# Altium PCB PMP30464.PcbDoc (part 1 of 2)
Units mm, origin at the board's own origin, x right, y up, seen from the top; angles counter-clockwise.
Board outline 89.03 x 50.29 mm, 4 copper layers (Top Layer, GND, Signal Layer, Bottom Layer), stack 2.028 mm thick; 80 components, 45 nets, 213 pads, 174 vias.
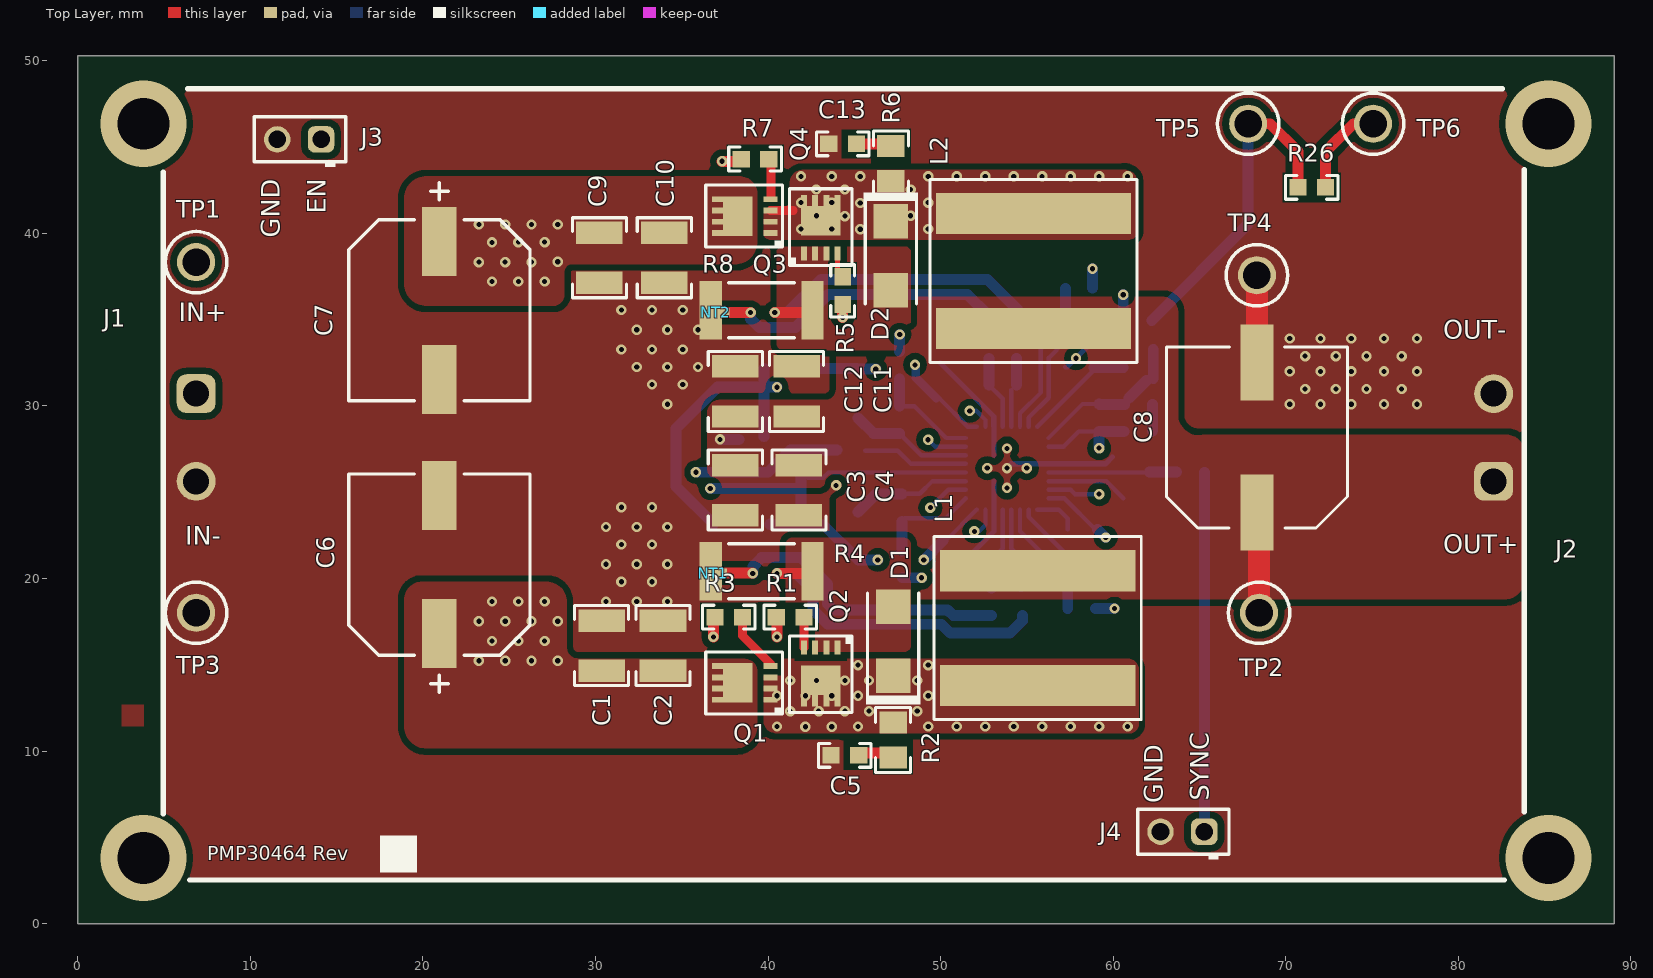
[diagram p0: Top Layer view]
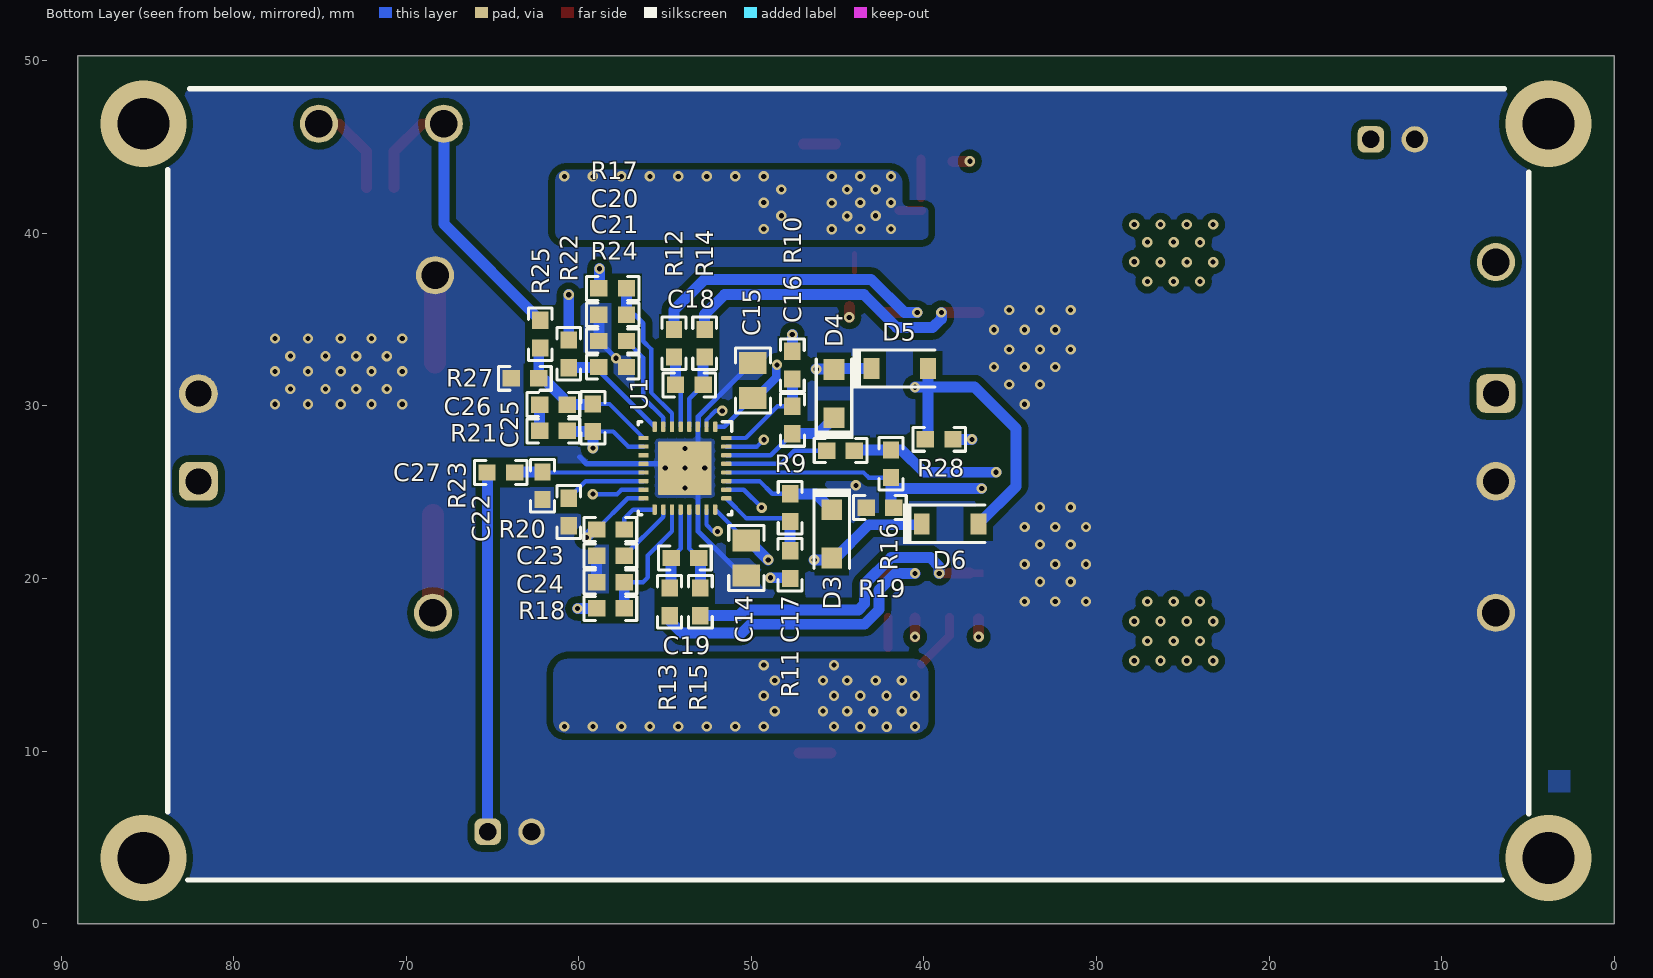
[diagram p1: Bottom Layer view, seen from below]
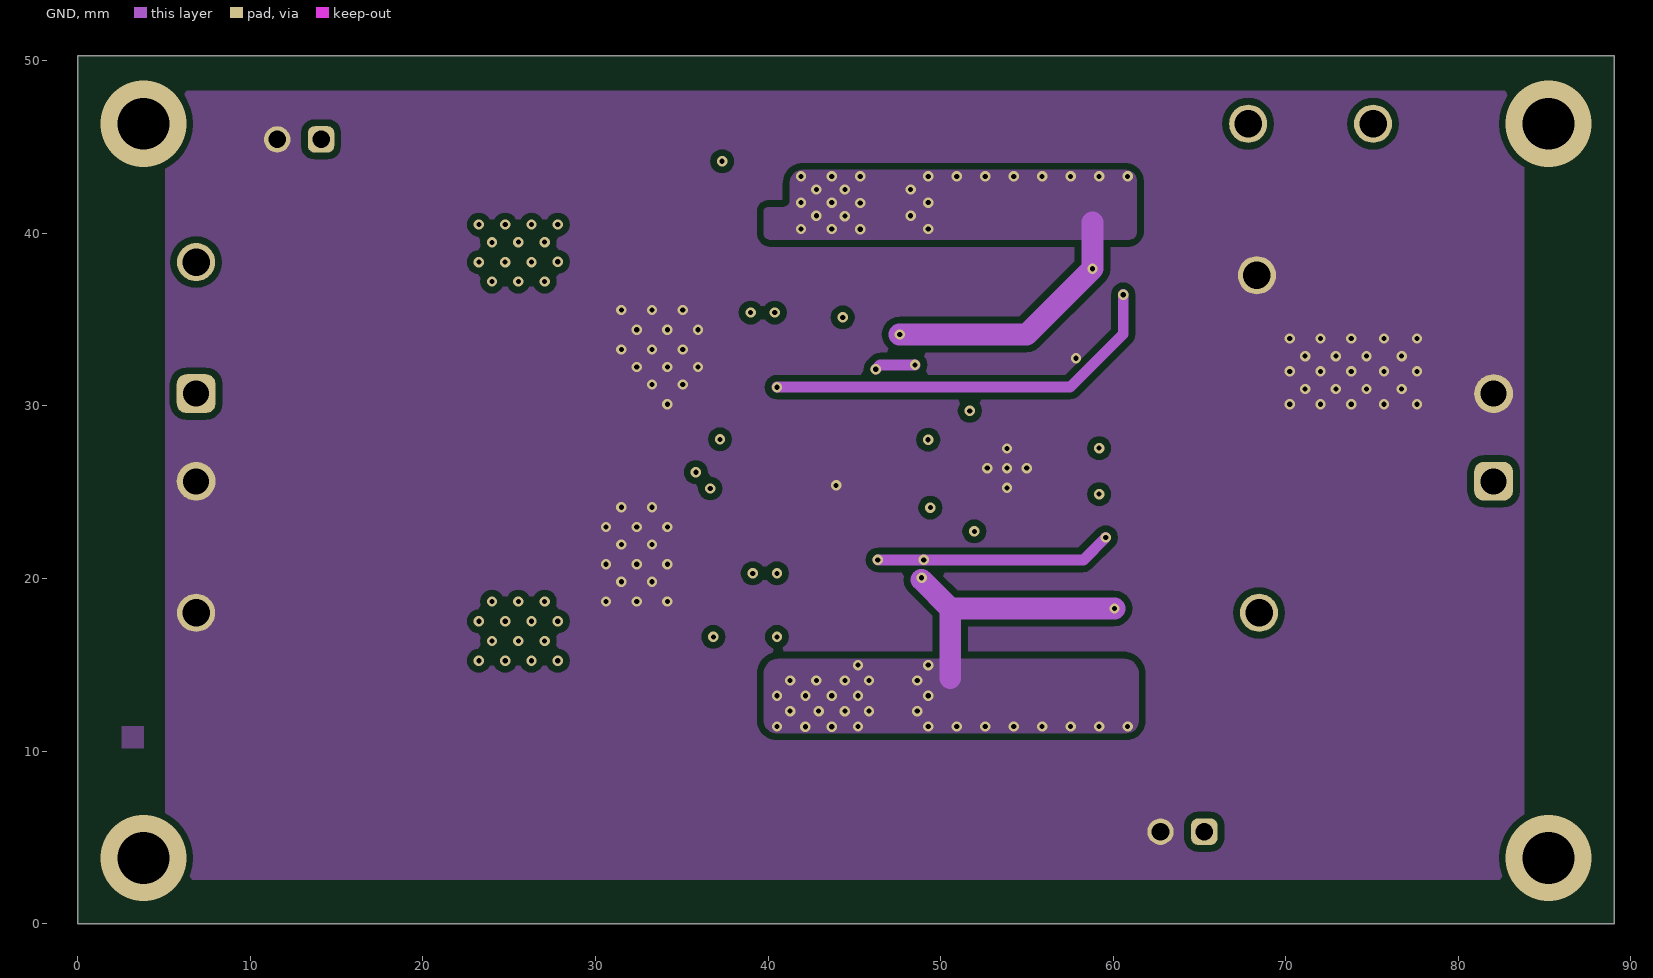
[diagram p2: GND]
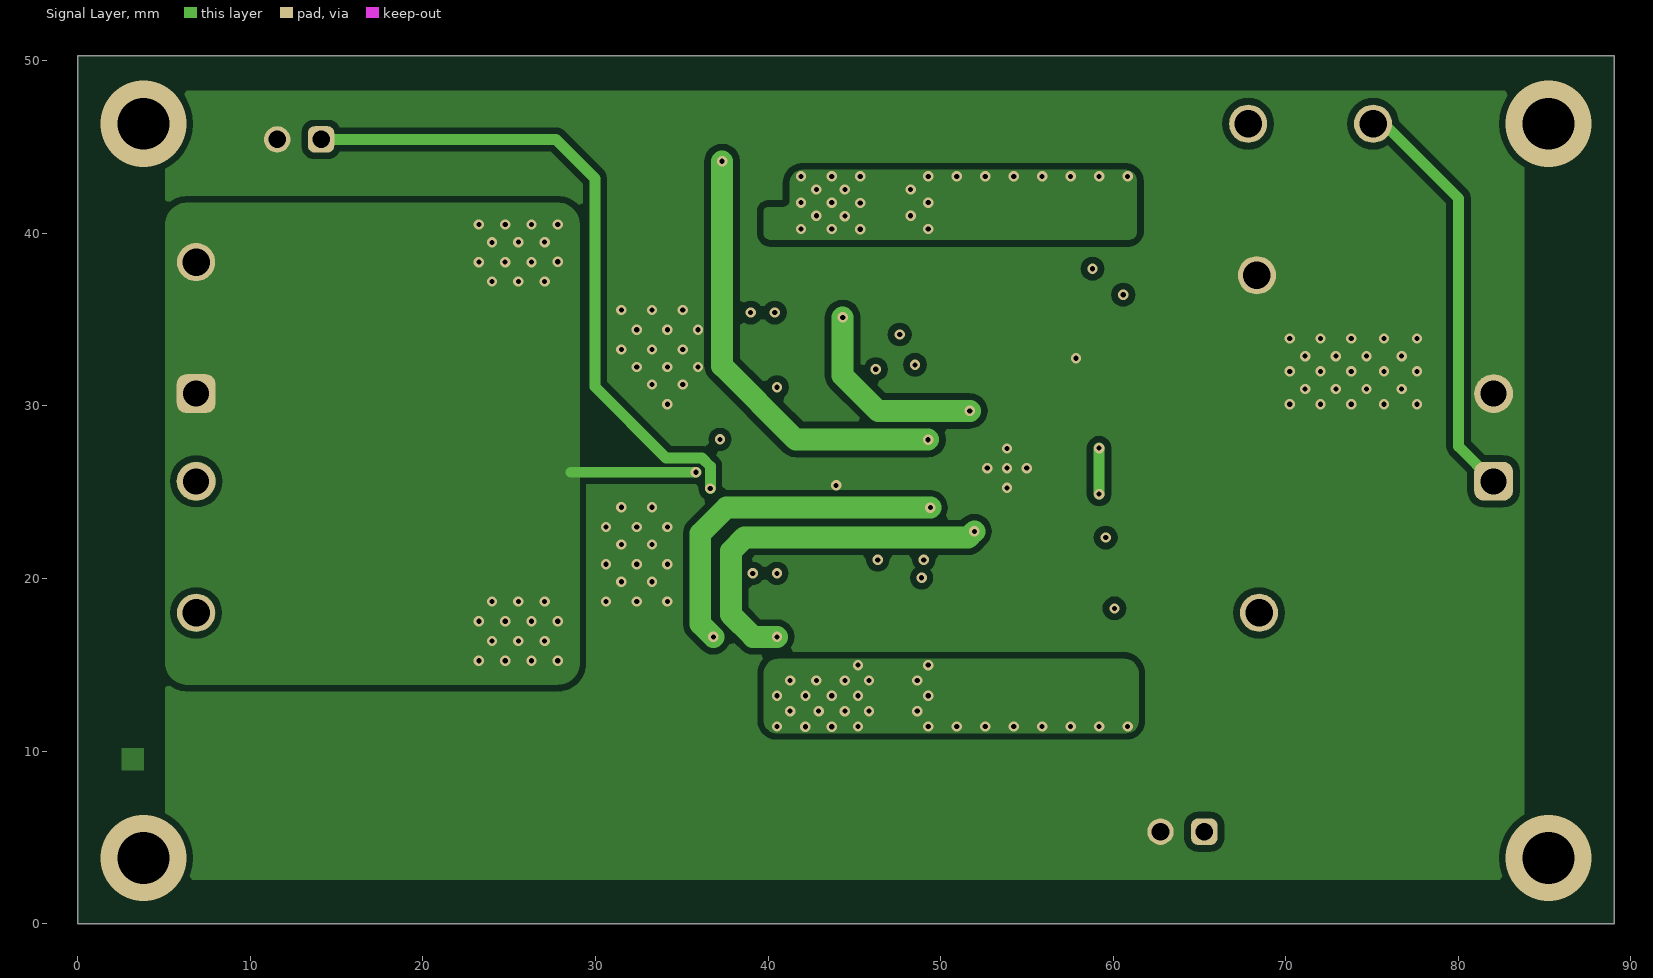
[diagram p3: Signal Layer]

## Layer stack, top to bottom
Top Solder: solder mask 0.0102, Solder Resist, Dk 3.5
Top Layer: signal copper 0.0356
Dielectric1: core 1.5037, FR-4, Dk 4.8
GND: signal copper 0.036
Dielectric 3: prepreg 0.127, Dk 4.2
Signal Layer: signal copper 0.036
Dielectric 2: core 0.254, Dk 4.2
Bottom Layer: signal copper 0.0356
Bottom Solder: solder mask 0.0102, Solder Resist, Dk 3.5

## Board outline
0,0 89.027,0 89.027,50.292 0,50.292

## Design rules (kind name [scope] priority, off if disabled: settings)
AcuteAngle [All] p1: minimum=4.50000000000000E+0001 checktracksonly=FALSE
AssemblyTestPointUsage [All] p1: valid=2
Clearance Clearance_Keepouts [((IsTrack Or IsArc) And Not InPoly) And IsFree and IsKeepOut vs ((IsTrack Or IsArc) And Not InPoly) And IsFree and IsKeepOut] p1: gap=0 ignorepadtopadclearanceinfootprint=FALSE
Clearance Clearance_BoardEdge_MountingHoles [OnCopper and InComponentClass('Mounting Holes') vs IsKeepOut] p2: gap=1.016 ignorepadtopadclearanceinfootprint=FALSE except(0: Arc-Hole Track-Hole SMDPad-Hole THPad-Hole Via-Hole Fill-Hole Poly-Hole Region-Hole Text-Hole)
Clearance Clearance_BoardEdge_Poly [OnCopper and InPoly vs IsKeepOut] p3: gap=0.635 ignorepadtopadclearanceinfootprint=FALSE except(0: Arc-Hole Track-Hole SMDPad-Hole THPad-Hole Via-Hole Fill-Hole Poly-Hole Region-Hole Text-Hole)
Clearance Clearance_BoardEdge [OnCopper and Not InComponentClass('Logo') and not InComponentClass('FiducialMark') and not InRegion(1000,500,4000,800) and Not IsKeepout vs IsKeepOut] p4: gap=1.905 ignorepadtopadclearanceinfootprint=FALSE except(0: Arc-Hole Track-Hole SMDPad-Hole THPad-Hole Via-Hole Fill-Hole Poly-Hole Region-Hole Text-Hole)
Clearance Clearance_Poly [InPolygon] p5: gap=0.381 ignorepadtopadclearanceinfootprint=FALSE except(0: Arc-Hole Track-Hole SMDPad-Hole THPad-Hole Via-Hole Fill-Hole Poly-Hole Region-Hole Text-Hole)
Clearance [All] p6: gap=0.2 ignorepadtopadclearanceinfootprint=FALSE except(0: Arc-Hole Track-Hole SMDPad-Hole THPad-Hole Via-Hole Fill-Hole Poly-Hole Region-Hole Text-Hole)
ComponentClearance ComponentClearance_MountingHoles_FiducialMarks [InComponentClass('Mounting Holes') vs InComponentClass('FiducialMark')] p1: gap=1.27 collisioncheckmode=3 verticalgap=0.254 showdistances=FALSE
ComponentClearance ComponentClearance_Shunt [InComponentClass('Header') vs InComponentClass('Shunt')] p2: gap=0 collisioncheckmode=3 verticalgap=0 showdistances=FALSE
ComponentClearance ComponentClearance_Logo [InComponentClass('Logo')] p3: gap=1.27 collisioncheckmode=3 verticalgap=0.254 showdistances=FALSE
ComponentClearance ComponentClearance_ScrewToNut [(HasFootprint('NY PMS 440 0025 PH')) vs (HasFootprint('Keystone_1902C'))] p4: gap=0.127 collisioncheckmode=3 verticalgap=0.254 showdistances=FALSE
ComponentClearance ComponentClearance_MountingHoles [InComponentClass('Mounting Holes')] p5: gap=6.35 collisioncheckmode=3 verticalgap=2540 showdistances=FALSE
ComponentClearance ComponentClearance_SmallPassives [HasFootprint('0201*') or HasFootprint('0402*') or HasFootprint('0508') or HasFootprint('0603*') or HasFootprint('0612') or HasFootprint('0805*') or HasFootprint('0815*') or HasFootprint('0830*') or HasFootprint('1206*') or HasFootprint('1210*') or HasFootprint('1808*') or HasFootprint('1812*') or HasFootprint('1825*') or HasFootprint('2010*') or HasFootprint('2220*') or HasFootprint('2225*') or HasFootprint('2512*') or HasFootprint('2728*') or HasFootprint('3518*') vs HasFootprint('0201*') or HasFootprint('0402*') or HasFootprint('0508') or HasFootprint('0603*') or HasFootprint('0612') or HasFootprint('0805*') or HasFootprint('0815*') or HasFootprint('0830*') or HasFootprint('1206*') or HasFootprint('1210*') or HasFootprint('1808*') or HasFootprint('1812*') or HasFootprint('1825*') or HasFootprint('2010*') or HasFootprint('2220*') or HasFootprint('2225*') or HasFootprint('2512*') or HasFootprint('2728*') or HasFootprint('3518*')] p6: gap=0.508 collisioncheckmode=3 verticalgap=0.254 showdistances=FALSE
ComponentClearance ComponentClearance_THtoSMT [IsThruComponent vs IsSMTComponent] p7: gap=2.54 collisioncheckmode=3 verticalgap=0.762 showdistances=FALSE
ComponentClearance ComponentClearance_THtoTH [IsThruComponent vs IsThruComponent] p8: gap=3 collisioncheckmode=3 verticalgap=0.762 showdistances=FALSE
ComponentClearance [All] p9: gap=1.016 collisioncheckmode=3 verticalgap=0.254 showdistances=FALSE
DiffPairsRouting [All] p1: maxlimit=2.54 minlimit=0.254 mostfreqgap=0.254 toplayer_minwidth=0.381 toplayer_maxwidth=0.381 toplayer_prefwidth=0.381 midlayer1_minwidth=0.381 midlayer1_maxwidth=0.381 midlayer1_prefwidth=0.381 midlayer2_minwidth=0.381 midlayer2_maxwidth=0.381 midlayer2_prefwidth=0.381 bottomlayer_minwidth=0.381 bottomlayer_maxwidth=0.381 bottomlayer_prefwidth=0.381 maxuncoupledlength=25.4
FabricationTestPointUsage TestPointUsage [All] p1: valid=2 allowmultiple=FALSE
FabricationTestpoint Testpoint [All] p1: side=3 testpointundercomponent=TRUE minsize=1.016 maxsize=2.54 preferedsize=1.524 minholesize=0 maxholesize=1.016 preferedholesize=0.813 testpointgrid=0.025 allowsidetop=TRUE allowsidebottom=TRUE usegrid=TRUE gridtolerance=0
FanoutControl Fanout_LCC [IsLCC] p1: bgadir=Out bgaviamode=Centered fanoutstyle=Auto fanoutdirection=Alternating viagrid=0.025 // Fanout_LCC (Default Rule)
FanoutControl Fanout_BGA [IsBGA] p2: bgadir=Out bgaviamode=Centered fanoutstyle=Auto fanoutdirection=Alternating viagrid=0.025 // Fanout_BGA (Default Rule)
FanoutControl Fanout_Default [All] p4: bgadir=Out bgaviamode=Centered fanoutstyle=Auto fanoutdirection=Alternating viagrid=0.025 // Fanout_Default (Default Rule)
FanoutControl Fanout_Small [(CompPinCount < 5)] p5: bgadir=Out bgaviamode=Centered fanoutstyle=Auto fanoutdirection=OutThenIn viagrid=0.025 // Fanout_Small (Default Rule)
HoleSize [All] p1: absolutevalues=TRUE maxlimit=6.375 minlimit=0.3 maxpercent=80.000 minpercent=20.000
MinimumAnnularRing MinimumAnnularRing_ThermalPadVias [IsVia and InAnyComponent] p1: minimumring=0.15
MinimumAnnularRing [All] p2: minimumring=0.15
MinimumSolderMaskSliver MinimumSolderMaskSliver_Logo [InComponentClass('Logo') vs InComponentClass('Logo')] p1: minsoldermaskwidth=0.018
MinimumSolderMaskSliver [All] p2: minsoldermaskwidth=0.1
PlaneConnect [All] p1: planeconnectstyle=Relief reliefexpansion=0.254 reliefentries=4 reliefconductorwidth=0.254 reliefairgap=0.254
PolygonConnect [All] p1: connectstyle=Direct reliefconductorwidth=0.254 reliefentries=4 polygonreliefangle="90 Angle" airgapwidth=0.254
RoutingVias ThermalPadVias [IsVia and InAnyComponent] p1: holewidth=0.2 width=0.5 viastyle="Through Hole" minholewidth=0.3 minwidth=0.6 maxholewidth=0.33 maxwidth=0.6
RoutingVias [All] p2: holewidth=0.3 width=0.6 viastyle="Through Hole" minholewidth=0.3 minwidth=0.6 maxholewidth=1.016 maxwidth=1.651
SilkToBoardRegionClearance [Not ((IsComment or IsDesignator) And (Hide <> 'False')) and not InRegion(1000,500,4000,800)] p1:
SilkToSilkClearance SilkToSilkClearance_Pb-FreeLogo [(HasFootprint('Pb-Free_Overlay_Medium') OR HasFootprint('Pb-Free_Overlay_Small')) vs (HasFootprint('Pb-Free_Overlay_Medium') OR HasFootprint('Pb-Free_Overlay_Small'))] p1: silktosilkclearance=0
SilkToSilkClearance [All] p2: silktosilkclearance=0.102
SilkToSolderMaskClearance SilkToComonentPadClearance [IsPad and InAnycomponent] p1: minsilkscreentomaskgap=0.127 clearancetoexposedcopper=TRUE
SilkToSolderMaskClearance "Silk to Solder Mask Opening" [All] p2: minsilkscreentomaskgap=0.102 clearancetoexposedcopper=FALSE
SolderMaskExpansion [All] p1: expansion=0.05
Width [All] p1: maxlimit=2.54 minlimit=0.152 preferedwidth=0.254 checkconnectedcopper=TRUE
15 further rules are at their usual default settings.

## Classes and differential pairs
component class Header: J3 J4

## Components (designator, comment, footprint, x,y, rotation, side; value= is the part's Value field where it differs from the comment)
C1 "GRM32DC72A475KE01L" 1210_220 30.351,16.111 r90 top value=4.7uF
C2 "GRM32DC72A475KE01L" 1210_220 33.907,16.111 r90 top value=4.7uF
C3 "GRM32DR71E106KA12L" 1210_220 38.098,25.128 r270 top value=10uF
C4 "GRM32DR71E106KA12L" 1210_220 41.781,25.128 r270 top value=10uF
C5 "GCM1885C2A102JA16D" 0603 44.448,9.761 r180 top value=1000pF
C6 "PCR1J101MCL1GS" CR_1000x1270 20.953,20.81 r90 top value=100uF
C7 "PCR1J101MCL1GS" CR_1000x1270 20.953,35.542 r270 top value=100uF
C8 "16SVP330M" SM_RADIAL_10AMM 68.324,28.176 r90 top value=330uF
C9 "GRM32DC72A475KE01L" 1210_220 30.224,38.59 r270 top value=4.7uF
C10 "GRM32DC72A475KE01L" 1210_220 33.983,38.59 r270 top value=4.7uF
C11 "GRM32DR71E106KA12L" 1210_220 41.654,30.843 r90 top value=10uF
C12 "GRM32DR71E106KA12L" 1210_220 38.098,30.843 r90 top value=10uF
C13 "GCM1885C2A102JA16D" 0603 44.321,45.194 r180 top value=1000pF
C14 "GRM21BR71C475KA73L" 0805_HV 50.29,21.191 r90 bottom value=4.7uF
C15 "GRM21BR71C475KA73L" 0805_HV 49.909,31.478 r90 bottom value=4.7uF
C16 "GRM188R71C474KA88D" 0603 47.623,29.192 r270 bottom value=0.47uF
C17 "GRM188R71C474KA88D" 0603 47.75,24.112 r270 bottom value=0.47uF
C18 "GRM188R71E102KA01D" 0603 53.592,31.224 r180 bottom value=1000pF
C19 "GRM188R71E102KA01D" 0603 53.846,21.191 r180 bottom value=1000pF
C20 "GRM188R71H202KA01D" 0603 58.037,35.288 r0 bottom value=2000pF
C21 "GRM185R61C105KE44D" 0603 58.037,33.764 r0 bottom value=1uF
C22 "GRM188R71C474KA88D" 0603 60.577,23.858 r90 bottom value=0.47uF
C23 "GRM185R61C105KE44D" 0603 58.164,21.318 r0 bottom value=1uF
C24 "GRM188R71H202KA01D" 0603 58.164,19.794 r0 bottom value=2000pF
C25 "GRM1885C1H100JA01D" 0603 59.18,29.319 r90 bottom value=10pF
C26 "GRM188R71E222KA01D" 0603 61.466,30.081 r180 bottom value=2200pF
C27 "GRM1885C2A101JA01D" 0603 64.514,26.144 r0 bottom value=100pF
D1 "B180-13-F" SMA 47.242,16.365 r90 top value=80V
D2 "B180-13-F" SMA 47.115,38.717 r270 top value=80V
D3 "PMEG6010CEH,115" SOD-123F 45.337,22.588 r270 bottom value=60V
D4 "PMEG6010CEH,115" SOD-123F 45.21,30.716 r90 bottom value=60V
D5 "1N4148W-7-F" SOD-123 41.402,32.17 r180 bottom value=100V
D6 "1N4148W-7-F" SOD-123 38.481,23.174 r180 bottom value=100V
J1 "691236510002" Wurth_691236510002 6.856,28.176 r270 top
J2 "691236510002" Wurth_691236510002 82.04,28.176 r90 top
J3 "TSW-102-17-G-S" Samtec_TSW-102-17-x-S 12.825,45.448 r180 top
J4 "TSW-102-17-G-S" Samtec_TSW-102-17-x-S 64.008,5.334 r180 top
L1 "XAL1010-153MEB" XAL1010 55.624,17.127 r90 top value=15uH
L2 "XAL1010-153MEB" XAL1010 55.37,37.828 r270 top value=15uH
NT1 "Net-Tie" NetTie_0402 36.83,20.32 r0 top net-tie
NT2 "Net-Tie" NetTie_0402 36.957,35.433 r0 top net-tie
Q1 "BSZ070N08LS5" PG-TSDSON-8 38.606,13.952 r180 top value=60V
Q2 "BSZ070N08LS5" PG-TSDSON-8 43.051,14.46 r270 top value=60V
Q3 "BSZ070N08LS5" PG-TSDSON-8 38.606,41.003 r180 top value=60V
Q4 "BSZ070N08LS5" PG-TSDSON-8 43.051,40.368 r90 top value=60V
R1 "ERJ-3GEY0R00V" 0603 41.273,17.762 r180 top value=0
R2 "CRCW08051R00FKEA" 0805_HV 47.242,10.65 r90 top value=1.00
R3 "ERJ-3GEY0R00V" 0603 37.717,17.762 r180 top value=0
R4 "ERJ-M1WSF10MU" 2512 39.622,20.429 r0 top value=0.01
R5 "ERJ-3GEY0R00V" 0603 44.321,36.685 r270 top value=0
R6 "CRCW08051R00FKEA" 0805_HV 47.115,44.051 r270 top value=1.00
R7 "ERJ-3GEY0R00V" 0603 39.241,44.305 r180 top value=0
R8 "ERJ-M1WSF10MU" 2512 39.622,35.542 r0 top value=0.01
R9 "CRCW06031R00JNEA" 0603 44.829,27.414 r180 bottom value=1.0
R10 "ERJ-3GEY0R00V" 0603 47.623,32.367 r90 bottom value=0
R11 "ERJ-3GEY0R00V" 0603 47.75,20.81 r90 bottom value=0
R12 "CRCW0603100RFKEA" 0603 54.481,33.637 r90 bottom value=100
R13 "CRCW0603100RFKEA" 0603 54.735,18.651 r270 bottom value=100
R14 "CRCW0603100RFKEA" 0603 52.703,33.637 r90 bottom value=100
R15 "CRCW0603100RFKEA" 0603 52.957,18.651 r270 bottom value=100
R16 "CRCW060349K9FKEA" 0603 41.908,26.652 r90 bottom value=49.9k
R17 "CRCW060336K5FKEA" 0603 58.037,36.812 r180 bottom value=36.5k
R18 "CRCW060336K5FKEA" 0603 58.164,18.27 r0 bottom value=36.5k
R19 "CRCW06033K92FKEA" 0603 42.545,24.112 r180 bottom value=3.92k
R20 "ERJ-3GEY0R00V" 0603 58.164,22.842 r0 bottom value=0
R21 "CRCW0603121KFKEA" 0603 61.466,28.557 r180 bottom value=121k
R22 "CRCW060330K9FKEA" 0603 60.579,33.02 r90 bottom value=30.9k
R23 "CRCW060316K2FKEA" 0603 62.101,25.382 r90 bottom value=16.2k
R24 "CRCW06034K99FKEA" 0603 58.039,32.258 r0 bottom value=4.99k
R25 "CRCW060349K9FKEA" 0603 62.23,34.163 r90 bottom value=49.9k
R26 "CRCW060349R9FKEA" 0603 71.501,42.672 r0 top value=49.9
R27 "CRCW06033K57FKEA" 0603 63.117,31.605 r180 bottom value=3.57k
R28 "CRCW060310R0FKEA" 0603 39.116,28.067 r180 bottom value=10.0
TP1 "5010" Keystone5010 6.856,38.336 r90 top
TP2 "5010" Keystone5010 68.451,18.016 r90 top
TP3 "5011" Keystone5011 6.856,18.016 r90 top
TP4 "5011" Keystone5011 68.324,37.574 r90 top
TP5 "5014" Keystone5014 67.818,46.355 r90 top
TP6 "5010" Keystone5010 75.057,46.355 r90 top
U1 "LM5119PSQX/NOPB" RTV0032A 53.846,26.398 r270 bottom

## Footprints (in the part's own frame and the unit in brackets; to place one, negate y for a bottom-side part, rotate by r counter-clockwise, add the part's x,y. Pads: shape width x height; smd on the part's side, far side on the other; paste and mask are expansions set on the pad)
0603 [mm] "0603 from SM-752 data"
  rect 1x0.95 smd: 1(-0.8,0) 2(0.8,0)
  silkscreen extent -1.52,-0.69 1.52,0.69, body extent -0.87,-0.47 0.87,0.47, height 1
0805_HV [mil] "0805 with 30mil clearance between pads"
  rect 50x63 smd: 1(-40,0) 2(40,0)
  silkscreen extent -74,-40 74,40, body extent -43,-29 43,29, height 57
1210_220 [mm] "1210"
  rect 1.3x2.7 smd: 1(-1.45,0) 2(1.45,0)
  silkscreen extent -2.32,-1.57 2.32,1.57, body extent -1.7,-1.35 1.7,1.35, height 2.2
2512 [mm] "Chip Resistor, Body 6.3x3.2mm, IPC Medium Density"
  rect 1.3x3.4 smd: 1(-2.95,0) 2(2.95,0)
  silkscreen extent -1.9,-1.6 1.9,1.6, body extent -3.22,-1.67 3.22,1.67, height 0.71
CR_1000x1270 [mm] "SMD, 2-Leads, Dia 10.5mm, Pin Spacing 8mm"
  rect 4x2 smd: 1(-4,0) 2(4,0)
  silkscreen extent -7.4,-5.25 5.25,5.25, body extent -5.25,-5.25 5.25,5.25, height 12.71
Keystone5010 [mil] "Keystone Multipurpose loops"
  round 87 hole 63: 1(0,0)
  silkscreen extent -70,-70 70,70, body extent -63,-63 63,62, height 319
Keystone5011 [mil] "Keystone Multipurpose loops"
  round 87 hole 63: 1(0,0)
  silkscreen extent -70,-70 70,70, body extent -63,-63 63,62, height 319
Keystone5014 [mil] "Keystone Multipurpose loops"
  round 87 hole 63: 1(0,0)
  silkscreen extent -70,-70 70,70, body extent -63,-63 63,62, height 319
NetTie_0402 [mm] "Net Tie 0402 size"
  rect 0.6x0.5 smd paste-0.5: 1(-0.5,0) 2(0.5,0)
  Top Layer region: -0.279,0.203 0.279,0.203 0.279,-0.203 -0.279,-0.203
PG-TSDSON-8 [mm] "Infineon recommended land pattern"
  rect 0.8x0.34 smd: 1(-1.538,0.975) 2(-1.538,0.325) 3(-1.538,-0.325) 4(-1.538,-0.975)
  rect 0.65x0.34 smd: 5(1.538,-0.975) 6(1.538,-0.325) 7(1.538,0.325) 8(1.538,0.975)
  rect 1.71x2.29 smd: 9(0.358,0)
  silkscreen extent -2.22,-1.8 2.22,1.8, body extent -1.7,-1.7 1.7,1.7, height 1.1
RTV0032A [mm] "QFN, 32-Leads, Body 5x5mm, Pitch 0.5mm"
  rrect40% 0.6x0.25 smd: 1(-2.4,1.75) 2(-2.4,1.25) 3(-2.4,0.75) 4(-2.4,0.25) 5(-2.4,-0.25) 6(-2.4,-0.75) 7(-2.4,-1.25) 8(-2.4,-1.75) 17(2.4,-1.75) 18(2.4,-1.25) 19(2.4,-0.75) 20(2.4,-0.25) 21(2.4,0.25) 22(2.4,0.75) 23(2.4,1.25) 24(2.4,1.75)
  rrect40% 0.25x0.6 smd: 9(-1.75,-2.4) 10(-1.25,-2.4) 11(-0.75,-2.4) 12(-0.25,-2.4) 13(0.25,-2.4) 14(0.75,-2.4) 15(1.25,-2.4) 16(1.75,-2.4) 25(1.75,2.4) 26(1.25,2.4) 27(0.75,2.4) 28(0.25,2.4) 29(-0.25,2.4) 30(-0.75,2.4) 31(-1.25,2.4) 32(-1.75,2.4)
  rrect3% 3.1x3.1 smd paste-1.55: 33(0,0)
  silkscreen extent -2.7,-2.7 2.7,2.7, body extent -2.55,-2.55 2.55,2.55, height 0.81
Samtec_TSW-102-17-x-S [mm] "Header, 2.54mm, 2x1, TH"
  rrect50% 1.53x1.53 hole 1.02: 1(-1.27,0)
  round 1.53 hole 1.02: 2(1.27,0)
  silkscreen extent -2.7,-1.3 2.6,1.6, body extent -2.67,-1.27 2.54,1.27, height 18.29
SM_RADIAL_10AMM [mm] "10 x 7.9mm:  Sanyo Oscon F8"
  rect 4.4x1.9 smd: 1(-4.35,0) 2(4.35,0)
  silkscreen extent -5.25,-5.25 5.25,5.25, body extent -5.25,-5.25 5.25,5.25, height 8
SMA [mm] "Molded Diode, 2-Leads, Body 4.3x2.6mm, IPC Medium Density, based on OnSemi component dimensions and land pattern"
  rect 2x2 smd: 1(-2,0) 2(2,0)
  silkscreen extent -3.66,-1.57 2.79,1.57, body extent -2.6,-1.3 2.6,1.3, height 2.42
SOD-123 [mm] "On Semi recommended land pattern"
  rect 0.915x1.22 smd: 1(-1.637,0) 2(1.637,0)
  silkscreen extent -2.74,-1.17 2.03,1.17, body extent -1.93,-0.9 1.93,0.9, height 1.35
SOD-123F [mm] "NXP recommended land pattern"
  rect 1.2x1.2 smd paste-0.05: 1(-1.4,0) 2(1.4,0)
  silkscreen extent -2.64,-1.12 2.01,1.12, body extent -1.8,-0.85 1.8,0.85, height 1.2
Wurth_691236510002 [mm] "Terminal Block, 5.08mm, 2x1, R/A, TH"
  rrect50% 2.25x2.25 hole 1.5: 1(-2.54,0)
  round 2.25 hole 1.5: 2(2.54,0)
  body extent -5.68,-5.5 5.08,5.85, height 18
XAL1010 [mm] "COILCRAFT"
  rect 2.38x11.31 smd: 1(-3.325,0) 2(3.325,0)
  silkscreen extent -5.3,-6 5.3,6, body extent -5.25,-5.9 5.25,5.9, height 10

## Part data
C1 C2 C9 C10: library part CMP-0009182-2, "CAP, CERM, 4.7 uF, 100 V, +/- 10%, X7S, 1210", Cap_Case=1210, Manufacturer=MuRata, Supplier Part Number 1=81-GRM32DC72A475KE1L, TempCo=X7S, Tolerance_%=10%, Value1=Unknown, Value2=100V, ValueDisplayed=4.7uF
C3 C4 C11 C12: library part CMP-0009190-2, "CAP, CERM, 10 uF, 25 V, +/- 10%, X7R, 1210", Cap_Case=1210, Manufacturer=MuRata, Supplier Part Number 1=490-1867-1-ND, TempCo=X7R, Tolerance_%=10%, Value1=Unknown, Value2=25V, ValueDisplayed=10uF
C5 C13: library part CMP-0007131-4, "CAP, CERM, 1000 pF, 100 V, +/- 5%, C0G/NP0, AEC-Q200 Grade 1, 0603", Cap_Case=0603, Manufacturer=MuRata, Supplier Part Number 1=490-4772-1-ND, TempCo=C0G/NP0, Tolerance_%=5%, Value1=Unknown, Value2=100V, ValueDisplayed=DNP
C6 C7: library part CMP-0012274-3, "CAP, Aluminum Polymer, 100 uF, 63 V, +/- 20%, 0.024 ohm, SMD, 2-Leads, Dia 10.5mm, Pin Spacing 8mm SMD", Cap_Case=10x12.7mm, Manufacturer=Nichicon, Supplier Part Number 1=493-13783-1-ND, Tolerance_%=20%, Value1="0.024 ohm", Value2=63V, ValueDisplayed=100uF
C8: library part CMP-0012084-3, "CAP, Aluminum Polymer, 330 uF, 16 V, +/- 20%, 0.016 ohm, 10x10.3 SMD", Cap_Case=10.3x10.3x12.6, Manufacturer=Panasonic, Tolerance_%=20%, Value1="0.016 ohm", Value2=16V, ValueDisplayed=330uF
C14 C15: library part CMP-0008334-2, "CAP, CERM, 4.7 uF, 16 V, +/- 10%, X7R, 0805", Cap_Case=0805, Manufacturer=MuRata, Supplier Part Number 1=490-4522-1-ND, TempCo=X7R, Tolerance_%=10%, Value1="0.006 ohm", Value2=16V, ValueDisplayed=4.7uF
C16 C17 C22: library part CMP-0007398-2, "CAP, CERM, 0.47 uF, 16 V, +/- 10%, X7R, 0603", Cap_Case=0603, Manufacturer=MuRata, Supplier Part Number 1=490-3295-1-ND, TempCo=X7R, Tolerance_%=10%, Value1=Unknown, Value2=16V, ValueDisplayed=0.47uF
C18 C19: library part CMP-0007402-2, "CAP, CERM, 1000 pF, 25 V, +/- 10%, X7R, 0603", Cap_Case=0603, Manufacturer=MuRata, Supplier Part Number 1=GRM188R71E102KA01D-ND, TempCo=X7R, Tolerance_%=10%, Value1=Unknown, Value2=25V, ValueDisplayed=1000pF
C20 C24: library part CMP-0007441-5, "CAP, CERM, 2000 pF, 50 V, +/- 10%, X7R, 0603", Cap_Case=0603, Manufacturer=MuRata, TempCo=X7R, Tolerance_%=10%, Value1=Unknown, Value2=50V, ValueDisplayed=2000pF
C21 C23: library part CMP-0007157-5, "CAP, CERM, 1 uF, 16 V, +/- 10%, X5R, 0603", Cap_Case=0603, Manufacturer=MuRata, Supplier Part Number 1=490-3894-1-ND, TempCo=X5R, Tolerance_%=10%, Value1=Unknown, Value2=16V, ValueDisplayed=1uF
C25: library part CMP-0007170-4, "CAP, CERM, 10 pF, 50 V, +/- 5%, C0G/NP0, 0603", Cap_Case=0603, Manufacturer=MuRata, Supplier Part Number 1=490-1403-1-ND, TempCo=C0G/NP0, Tolerance_%=5%, Value1=Unknown, Value2=50V, ValueDisplayed=10pF
C26: library part CMP-0007414-4, "CAP, CERM, 2200 pF, 25 V, +/- 10%, X7R, 0603", Cap_Case=0603, Manufacturer=MuRata, Supplier Part Number 1=GRM188R71E222KA01D-ND, TempCo=X7R, Tolerance_%=10%, Value1=Unknown, Value2=25V, ValueDisplayed=2200pF
C27: library part CMP-0007237-4, "CAP, CERM, 100 pF, 100 V, +/- 5%, C0G/NP0, 0603", Cap_Case=0603, Manufacturer=MuRata, Supplier Part Number 1=490-1351-1-ND, TempCo=C0G/NP0, Tolerance_%=5%, Value1=Unknown, Value2=100V, ValueDisplayed=100pF
D1 D2: library part CMP-0028393-1, "Diode, Schottky, 80 V, 1 A, SMA", Manufacturer="Diodes Inc.", Supplier Part Number 1=B180-FDICT-ND, Value1=1A, Value2=0.79V
D3 D4: library part CMP-0028377-1, "Diode, Schottky, 60 V, 1 A, SOD-123F", Manufacturer=Nexperia, Supplier Part Number 1=568-4104-1-ND, Value1=1A, Value2=0.57V
D5 D6: library part CMP-0029001-1, "Diode, Ultrafast, 100 V, 0.15 A, SOD-123", Manufacturer="Diodes Inc.", Supplier Part Number 1=1N4148W-FDICT-ND, Value1=0.15A, Value2=1.25V
J1 J2: library part CMP-0079044-1, "Terminal Block, 5.08mm, 2x1, R/A, TH", Color=Green, Current_A=20A, Manufacturer="Wurth Elektronik", Supplier Part Number 1=732-10995-ND, Voltage_V=300V
J3 J4: library part CMP-0077742-1, "Header, 2.54mm, 2x1, Gold, TH", Color=Black, Manufacturer=Samtec, Supplier Part Number 1=SAM1061-02-ND
L1 L2: library part CMP-0061645-2, "Inductor, Shielded, Composite, 15 uH, 13.8 A, 0.02 ohm, SMD", Manufacturer=Coilcraft, Supplier Part Number 1=994-XAL1010-153MEB, Value1="0.02 ohm", Value2=13.8A, ValueDisplayed=15uH
NT1 NT2: library part CMP-0078142-1, "Single point connection between nets.", Manufacturer=N/A
Q1 Q2 Q3 Q4: library part CMP-0000792-1, "MOSFET, N-CH, 60 V, 17 A, PG-TSDSON-8", Alternate Manufacturer=None, Manufacturer="Infineon Technologies", Supplier Part Number 1=BSZ042N06NSCT-ND, Value2="27 nC"
R1 R3 R5 R7 R10 R11: library part CMP-0025874-2, "RES, 0, 5%, 0.1 W, 0603", Manufacturer=Panasonic, Power_W=100mW, Supplier Part Number 1=P0.0GCT-ND, TempCo="600 ppm/C", Tolerance_%=5%, Value2=0.1W, Value_Code=0000, ValueDisplayed=0
R2 R6: library part CMP-0021009-3, "RES, 1.00, 1%, 0.125 W, AEC-Q200 Grade 0, 0805", Manufacturer=Vishay-Dale, Power_W=125mW, Supplier Part Number 1=72M6849, TempCo="100 ppm/C", Tolerance_%=1%, Value2=0.125W, Value_Code=1R00, ValueDisplayed=DNP
R4 R8: library part CMP-0015807-2, "RES, 0.01, 1%, 1 W, 2512", Manufacturer=Panasonic, Power_W=1W, Supplier Part Number 1=P10MCT-ND, TempCo="100 ppm/C", Tolerance_%=1%, Value_Code=R010, ValueDisplayed=0.01
R9: library part CMP-0025743-2, "RES, 1.0, 5%, 0.1 W, 0603", Manufacturer=Vishay-Dale, Power_W=100mW, Supplier Part Number 1=541-1.0GCT-ND, TempCo="200 ppm/C", Tolerance_%=5%, Value2=0.1W, Value_Code=1R00, ValueDisplayed=1.0
R12 R13 R14 R15: library part CMP-0021991-2, "RES, 100, 1%, 0.1 W, 0603", Manufacturer=Vishay-Dale, Power_W=100mW, Supplier Part Number 1=541-100HCT-ND, TempCo="100 ppm/C", Tolerance_%=1%, Value2=0.1W, Value_Code=100R, ValueDisplayed=100
R16 R25: library part CMP-0022447-4, "RES, 49.9 k, 1%, 0.1 W, AEC-Q200 Grade 0, 0603", Manufacturer=Vishay-Dale, Power_W=100mW, Supplier Part Number 1=541-49.9KHCT-ND, TempCo="100 ppm/C", Tolerance_%=1%, Value2=0.1W, Value_Code=49k9, ValueDisplayed=49.9k
R17 R18: library part CMP-0022356-4, "RES, 36.5 k, 1%, 0.1 W, AEC-Q200 Grade 0, 0603", Manufacturer=Vishay-Dale, Power_W=100mW, Supplier Part Number 1=541-36.5KHCT-ND, TempCo="100 ppm/C", Tolerance_%=1%, Value2=0.1W, Value_Code=36k5, ValueDisplayed=36.5k
R19: library part CMP-0022383-4, "RES, 3.92 k, 1%, 0.1 W, AEC-Q200 Grade 0, 0603", Manufacturer=Vishay-Dale, Power_W=100mW, Supplier Part Number 1=541-3.92KHCT-ND, TempCo="100 ppm/C", Tolerance_%=1%, Value2=0.1W, Value_Code=3k92, ValueDisplayed=3.92k
R20: library part CMP-0025874-2, "RES, 0, 5%, 0.1 W, 0603", Manufacturer=Panasonic, Power_W=100mW, Supplier Part Number 1=P0.0GCT-ND, TempCo="600 ppm/C", Tolerance_%=5%, Value2=0.1W, Value_Code=0000, ValueDisplayed=DNP
R21: library part CMP-0022024-4, "RES, 121 k, 1%, 0.1 W, AEC-Q200 Grade 0, 0603", Manufacturer=Vishay-Dale, Power_W=100mW, Supplier Part Number 1=541-121KHCT-ND, TempCo="100 ppm/C", Tolerance_%=1%, Value2=0.1W, Value_Code=121k
R22: library part CMP-0022325-4, "RES, 30.9 k, 1%, 0.1 W, AEC-Q200 Grade 0, 0603", Manufacturer=Vishay-Dale, Power_W=100mW, Supplier Part Number 1=541-30.9KHCT-ND, TempCo="100 ppm/C", Tolerance_%=1%, Value2=0.1W, Value_Code=30k9, ValueDisplayed=30.9k
R23: library part CMP-0022079-4, "RES, 16.2 k, 1%, 0.1 W, AEC-Q200 Grade 0, 0603", Manufacturer=Vishay-Dale, Power_W=100mW, Supplier Part Number 1=541-16.2KHCT-ND, TempCo="100 ppm/C", Tolerance_%=1%, Value2=0.1W, Value_Code=16k2, ValueDisplayed=16.2k
R24: library part CMP-0022458-4, "RES, 4.99 k, 1%, 0.1 W, AEC-Q200 Grade 0, 0603", Manufacturer=Vishay-Dale, Power_W=100mW, Supplier Part Number 1=541-4.99KHCT-ND, TempCo="100 ppm/C", Tolerance_%=1%, Value2=0.1W, Value_Code=4k99, ValueDisplayed=4.99k
R26: library part CMP-0022448-4, "RES, 49.9, 1%, 0.1 W, AEC-Q200 Grade 0, 0603", Manufacturer=Vishay-Dale, Power_W=100mW, Supplier Part Number 1=541-49.9HCT-ND, TempCo="100 ppm/C", Tolerance_%=1%, Value2=0.1W, Value_Code=49R9, ValueDisplayed=49.9
R27: library part CMP-0022378-4, "RES, 3.57 k, 1%, 0.1 W, AEC-Q200 Grade 0, 0603", Manufacturer=Vishay-Dale, Power_W=100mW, Supplier Part Number 1=541-3.57KHCT-ND, TempCo="100 ppm/C", Tolerance_%=1%, Value2=0.1W, Value_Code=3k57, ValueDisplayed=3.57k
R28: library part CMP-0022003-4, "RES, 10.0, 1%, 0.1 W, AEC-Q200 Grade 0, 0603", Manufacturer=Vishay-Dale, Power_W=100mW, Supplier Part Number 1=541-10.0HCT-ND, TempCo="100 ppm/C", Tolerance_%=1%, Value2=0.1W, Value_Code=10R0, ValueDisplayed=10.0
TP1 TP2 TP6: library part CMP-0055147-1, "Test Point, Multipurpose, Red, TH", Color=Red, Manufacturer=Keystone, Supplier Part Number 1=36-5010-ND
TP3 TP4: library part CMP-0055148-1, "Test Point, Multipurpose, Black, TH", Color=Black, Manufacturer=Keystone, Supplier Part Number 1=36-5011-ND
TP5: library part CMP-0055151-1, "Test Point, Multipurpose, Yellow, TH", Color=Yellow, Manufacturer=Keystone, Supplier Part Number 1=36-5014-ND
U1: library part CMP-0066051-1, "5.5-65V Wide Vin, Current Mode Dual Synchronous Buck Controller, RTV0032A (WQFN-32)", Alternate Manufacturer="Texas Instruments", Alternate PartNumber=LM5119PSQ/NOPB

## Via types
v1: diameter 0.6, hole 0.3, Top Layer to Bottom Layer, 170 vias
v2: diameter 5, hole 3, Top Layer to Bottom Layer, 4 vias

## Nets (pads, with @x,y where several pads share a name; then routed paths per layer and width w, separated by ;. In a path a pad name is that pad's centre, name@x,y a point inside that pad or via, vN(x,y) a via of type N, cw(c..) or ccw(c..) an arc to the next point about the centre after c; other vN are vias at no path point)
COMP1: C25.1 R21.2 U1.10 U1.15 | length 11.4
  Signal Layer w0.635: v1(59.182,24.892) v1(59.182,27.559)
  Bottom Layer w0.254: U1.15@56.246,25.148 57.529,25.148 57.785,24.892 v1(59.182,24.892) ; U1.10@56.246,27.648 57.128,27.648 57.999,28.519 C25.1@59.18,28.519
  Bottom Layer w0.635: v1@59.18,27.561 C25.1@59.18,28.519 R21.2@60.628,28.519
CS1: D2.2 Q4.1 Q4.2 Q4.3 R8.2 R12.2 | length 19
  Top Layer w0.635: v1(40.384,35.415) 42.445,35.415 R8.2@42.572,35.542
  Bottom Layer w0.635: v1(40.384,35.415) 41.13,35.415 43.053,37.338 52.705,37.338 54.481,35.562 R12.2@54.481,34.437
CS2: D1.2 Q2.1 Q2.2 Q2.3 R4.2 R13.2 | length 18.9
  Top Layer w0.635: v1(40.511,20.302) R4.2@42.445,20.302
  Bottom Layer w0.635: v1(40.511,20.302) 41.636,20.302 42.599,19.339 42.599,18.196 43.442,17.354 50.046,17.354 50.566,16.833 54.013,16.833 54.735,17.556 R13.2@54.735,17.851
CSG1: NT2.2 R14.2 | length 18.6
  Top Layer w0.635: 36.799,35.415 v1(38.987,35.415)
  Bottom Layer w0.635: v1(38.987,35.415) 38.987,35.054 39.497,34.544 41.574,34.544 43.479,36.449 51.562,36.449 52.703,35.308 R14.2@52.703,34.437
CSG2: NT1.2 R15.2 | length 18.3
  Top Layer w0.635: NT1.2@37.33,20.32 v1@39.096,20.32
  Bottom Layer w0.635: v1(39.114,20.302) 39.114,20.699 39.624,21.209 41.91,21.209 43.434,19.685 43.434,18.542 43.787,18.189 50.391,18.189 50.729,17.851 R15.2@52.957,17.851
EN: J3.1 R16.1 R19.2 U1.28 | length 54.9
  Signal Layer w0.635: J3.1@14.095,45.448 27.704,45.448 29.972,43.18 29.972,31.115 34.09,26.997 36.16,26.997 36.649,26.508 v1(36.649,25.219)
  Bottom Layer w0.254: R16.1@42.289,25.852 43.202,25.852 43.498,26.148 U1.28@51.446,26.148
  Bottom Layer w0.635: v1(36.649,25.219) 41.627,25.219 41.7,25.146 ; R19.2@41.908,24.023 R16.1@41.908,25.852
GND: C1.2 C2.2 C3.2 C4.2 C5.2 C6.2 C7.2 C8.2 C9.2 C10.2 C11.2 C12.2 C13.2 C14.1 C15.2 C20.2 C21.2 C22.1 C23.2 C24.2 J1.2 J2.2 J3.2 J4.2 NT1.1 NT2.1 R4.1 R8.1 R19.1 R23.1 R24.1 R27.1 TP3.1 TP4.1 U1.3 U1.12 U1.22 U1.33 | length 29.5
  Top Layer w1.27: C8.2@68.324,32.526 TP4.1@68.324,37.574
  Bottom Layer w0.305: C15.2@49.972,32.494 53.075,29.391 53.075,28.819 U1.3@53.096,28.798 U1.33@53.096,27.148 ; C14.1@50.528,20.175 53.096,22.743 U1.22@53.096,23.998 U1.33@53.096,25.648 ; U1.33@54.096,26.648 U1.12@56.246,26.648 59.541,26.648 59.944,27.051 ; R24.1@57.239,32.258 57.331,32.258 C21.2@58.837,33.764
  Bottom Layer w0.635: C21.2@58.837,33.764 C20.2@58.837,35.288 ; C24.2@58.964,19.794 C23.2@58.964,21.318
  other v1: 30.607,18.669 32.385,18.669 34.163,18.669 31.496,19.812 33.274,19.812 30.607,20.828 32.385,20.828 34.163,20.828 31.496,21.971 33.274,21.971 30.607,22.987 32.385,22.987 34.163,22.987 31.496,24.13 33.274,24.13 53.846,25.255 43.942,25.4 52.703,26.398 53.846,26.398 54.989,26.398 53.846,27.541 34.163,30.099 70.231,30.099 72.009,30.099 73.787,30.099 75.692,30.099 77.597,30.099 71.12,30.988 72.898,30.988 74.676,30.988 76.708,30.988 33.274,31.242 35.052,31.242 70.231,32.004 72.009,32.004 73.787,32.004 75.692,32.004 77.597,32.004 32.385,32.258 34.163,32.258 35.941,32.258 57.839,32.766 71.12,32.893 72.898,32.893 74.676,32.893 76.708,32.893 31.496,33.274 33.274,33.274 35.052,33.274 70.231,33.909 72.009,33.909 73.787,33.909 75.692,33.909 77.597,33.909 32.385,34.417 34.163,34.417 35.941,34.417 31.496,35.56 33.274,35.56 35.052,35.56
HO1: R7.2 U1.31 | length 28.9
  Top Layer w0.635: v1(37.336,44.178) R7.2@38.314,44.178
  Signal Layer w1.27: v1(37.336,44.178) 37.336,32.323 41.61,28.049 v1(49.274,28.049)
  Bottom Layer w0.254: v1(49.274,28.049) 49.675,27.648 U1.31@51.446,27.648
HO2: R3.2 U1.26 | length 23.8
  Top Layer w0.635: v1(36.828,16.619) R3.2@36.828,17.673
  Signal Layer w1.27: v1(36.828,16.619) 36.068,17.379 36.068,22.606 37.574,24.112 v1(49.401,24.112)
  Bottom Layer w0.254: v1(49.401,24.112) 50.437,25.148 U1.26@51.446,25.148
LO1: R5.2 U1.2 | length 13.7
  Top Layer w0.635: v1(44.321,35.135) R5.2@44.321,35.758
  Signal Layer w1.27: v1(44.321,35.135) 44.321,31.763 46.384,29.7 46.402,29.718 v1(51.689,29.718)
  Bottom Layer w0.254: v1(51.689,29.718) 52.07,29.718 52.596,29.192 U1.2@52.596,28.798
LO2: R1.2 U1.23 | length 24.3
  Top Layer w0.635: v1(40.511,16.619) R1.2@40.511,17.724
  Signal Layer w1.27: v1(40.511,16.619) 39.134,16.619 37.846,17.907 37.846,21.59 38.635,22.379 51.597,22.379 v1(51.951,22.733)
  Bottom Layer w0.254: v1(51.951,22.733) 52.213,22.733 52.596,23.116 U1.23@52.596,23.998
NetC5_1: C5.1 R2.1 | length 1.9
  Top Layer w0.635: C5.1@45.375,9.888 R2.1@47.242,9.888
NetC13_1: C13.1 R6.1 | length 1.9
  Top Layer w0.635: C13.1@45.121,45.194 R6.1@46.988,45.194
NetC16_1: C16.1 R10.1 U1.32 | length 6.2
  Bottom Layer w0.254: C16.1@47.623,29.992 48.481,29.992 50.325,28.148 U1.32@51.446,28.148
  Bottom Layer w0.635: C16.1@47.623,29.992 R10.1@47.623,31.567
NetC16_2: C16.2 D4.1 U1.30 | length 7.1
  Bottom Layer w0.254: C16.2@47.623,28.392 48.867,27.148 U1.30@51.446,27.148
  Bottom Layer w0.635: D4.1@45.21,29.316 46.119,28.406 47.623,28.406 C16.2@47.623,28.392
NetC17_1: C17.1 D3.1 U1.27 | length 7
  Bottom Layer w0.254: C17.1@47.75,24.912 48.788,24.912 49.524,25.648 U1.27@51.446,25.648
  Bottom Layer w0.635: D3.1@45.21,23.861 46.261,24.912 C17.1@47.75,24.912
